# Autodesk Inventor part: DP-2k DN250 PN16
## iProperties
Created: 2009-08
Part Number: DP-2k DN250 PN16
Document SubType Name: Modelowanie
Designer: Marcin Pyzik
Author: Marcin Pyzik
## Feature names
1. Wyciągnięcie proste1 [Extrusion]
2. Faza1 [Chamfer]
3. Bryła wyprowadzona1 [Tagging]
